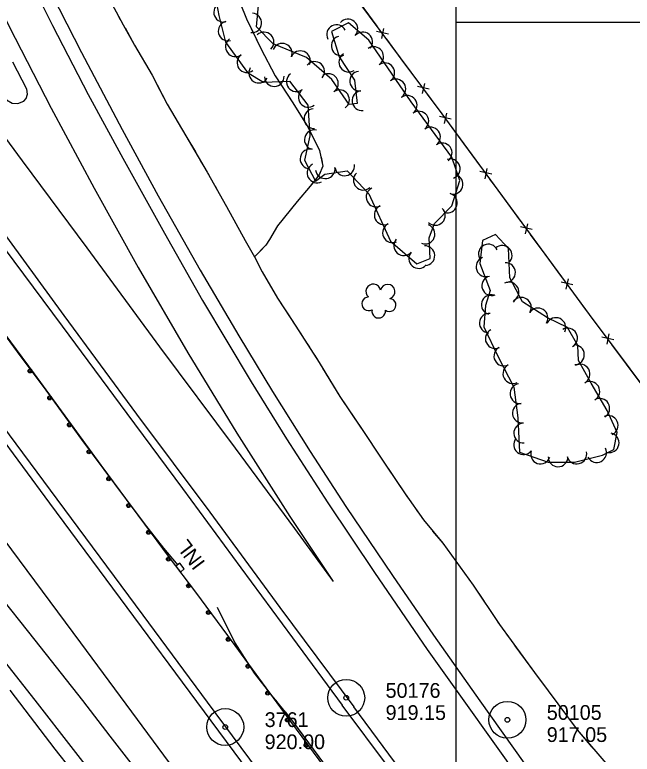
# Model space of a CAD drawing. Extents: x 353423 to 364002, y 127000 to 201942.
# Drawn here: x 359820.6 to 360071.5, y 131702.2 to 132002.9 of the extents above; entities that cross this region are included whole.
import ezdxf

# ---------------------------------------------------------------- set-up
doc = ezdxf.new("R2010")
doc.units = 0
for name, color, linetype in [('E_DTM_SlopeBottom', 7, 'Continuous'), ('E_DTM_SlopeTop', 7, 'Continuous'), ('E_FEN_Generic', 7, 'Continuous'), ('E_LAND_TreeLine', 7, 'Continuous'), ('E_MISCPROP', 7, 'Continuous'), ('E_RDWY_AsphConc', 7, 'Continuous'), ('E_STRUCT_WingWall', 7, 'Continuous')]:
    doc.layers.add(name, color=color, linetype=linetype)

msp = doc.modelspace()

# ---------------------------------------------------------------- linework, layer by layer
at = {"layer": 'E_DTM_SlopeBottom'}
for p, q in [((359972.44, 131995.06), (359967.62, 131996.12)), ((359969.73, 131993.27), (359970.62, 131997.4)), ((359986.31, 131970.87), (359987.2, 131975.01)), ((359989.01, 131972.66), (359984.2, 131973.72)), ((359995.24, 131958.78), (359996.15, 131962.91)), ((359997.95, 131960.55), (359993.14, 131961.64)), ((360014.4, 131938.07), (360009.59, 131939.15)), ((360011.68, 131936.29), (360012.59, 131940.42)), ((360028.18, 131913.83), (360029.08, 131917.96)), ((360030.89, 131915.61), (360026.08, 131916.69)), ((360047.39, 131893.16), (360042.57, 131894.24)), ((360044.67, 131891.38), (360045.57, 131895.51)), ((360061.27, 131868.99), (360062.14, 131873.13)), ((360063.97, 131870.79), (360059.15, 131871.83))]:
    msp.add_line(p, q, dxfattribs=at)
for points in [[(359994.23, 131962.69), (359952.2, 132019.47), (359914.96, 132070.63), (359879.25, 132119.71), (359869.92, 132132.28), (359846.86, 132192.53), (359828.18, 132241.38), (359813.12, 132280.33), (359807.45, 132296.37), (359796.4, 132325.26), (359763.05, 132412.67), (359729.64, 132499.02), (359699.93, 132578.43), (359671.73, 132653.26)], [(359967.82, 131998.38), (359961.08, 132007.48)], [(359977.66, 131985.09), (359971.73, 131993.09)], [(359984.39, 131975.99), (359977.66, 131985.09)], [(359994.23, 131962.69), (359988.31, 131970.7)], [(360168.57, 131726.41), (360146.27, 131756.69), (360118.24, 131794.76), (360087.55, 131836.32), (360054.15, 131881.02), (360015.47, 131933.65), (359994.23, 131962.69)], [(360003.11, 131950.55), (359997.23, 131958.59)], [(360009.79, 131941.42), (360003.11, 131950.55)], [(360019.57, 131928.08), (360015.47, 131933.65), (360013.68, 131936.1)], [(360026.27, 131918.95), (360019.57, 131928.08)], [(360036.07, 131905.62), (360030.17, 131913.65)], [(360042.77, 131896.5), (360036.07, 131905.62)], [(360052.57, 131883.18), (360046.67, 131891.2)], [(360059.33, 131874.09), (360054.15, 131881.02), (360052.57, 131883.18)], [(360069.23, 131860.85), (360063.27, 131868.82)], [(360076, 131851.78), (360069.23, 131860.85)], [(359887.91, 131776.33), (359889.48, 131777.56), (359887.63, 131779.92), (359886.06, 131778.68), (359887.91, 131776.33)]]:
    msp.add_lwpolyline(points, dxfattribs=at)
at = {"layer": 'E_DTM_SlopeTop'}
for points in [[(359296.04, 132656.2), (359327.36, 132613.62), (359357.21, 132573.34), (359387.83, 132532.04), (359420.96, 132487.16), (359453.44, 132443.29), (359480.05, 132407.27), (359517.09, 132357.33), (359543.42, 132321.88), (359571.35, 132284.17), (359599.99, 132245.46), (359627.75, 132207.82), (359655.85, 132169.95), (359684.1, 132131.8), (359713.89, 132091.57), (359740.72, 132055.1), (359769.42, 132016.5), (359798.55, 131977.39), (359823.57, 131943.56), (359849.91, 131908.1), (359879.42, 131867.94), (359910.1, 131826.75), (359934.24, 131793.99), (359949.98, 131772.5)], [(359894.52, 131723.73), (359866.32, 131761.93), (359834.77, 131804.35), (359801.8, 131849.06), (359771.18, 131890.36), (359741.61, 131930.36), (359706.83, 131977.37), (359677.25, 132017.15), (359645.21, 132060.41), (359616.57, 132099.29), (359584.47, 132142.49), (359551.44, 132186.98), (359516.16, 132234.78), (359477.26, 132287.18), (359438.91, 132339.08), (359394.26, 132399.62), (359356.73, 132450.28), (359318.1, 132502.23), (359283.37, 132549.19), (359243.7, 132602.83), (359207.65, 132651.41)], [(359449.12, 132409.2), (359470.8, 132379.85), (359494.5, 132347.87), (359517.49, 132316.9), (359547.17, 132276.9), (359572.24, 132242.9), (359598.91, 132206.77), (359623.16, 132174.01), (359647.03, 132141.86), (359674.62, 132104.55), (359700.41, 132069.65), (359726.69, 132034.19), (359755.34, 131995.76), (359785.73, 131954.75), (359813.39, 131917.61), (359840.54, 131880.58), (359870.11, 131840.52), (359899.85, 131800.63), (359928.33, 131761.92), (359958.37, 131721.52)], [(359458.15, 132391.51), (359482.94, 132357.62), (359509.06, 132322.72), (359533.32, 132290.35), (359554.33, 132261.68), (359577.87, 132229.81), (359599.59, 132200.53), (359624.12, 132167.31), (359650.84, 132131.46), (359672.46, 132102.12), (359694.57, 132072.22), (359715.85, 132043.32), (359739.28, 132011.9), (359764.96, 131977.01), (359794.26, 131937.73), (359816.26, 131908), (359839.86, 131876.35), (359866.08, 131840.78), (359888.69, 131810.32), (359912.39, 131778), (359933.4, 131749.61), (359953.69, 131722.15)], [(359898.92, 131723.42), (359872.8, 131758.76), (359846.3, 131794.45), (359818.43, 131832.09), (359795, 131863.74), (359772.17, 131894.54), (359743.48, 131933.36), (359717.7, 131968.37), (359690.1, 132005.9), (359664.2, 132040.3), (359638.9, 132074.46), (359610.49, 132113.12), (359579.6, 132154.64), (359555.84, 132186.89), (359530, 132221.9), (359503.11, 132258.09), (359475.08, 132296.24), (359444.41, 132337.76)], [(359868.2, 131719.43), (359847.41, 131747.54), (359825.57, 131776.88), (359796.6, 131815.87), (359765.6, 131857.67), (359742.12, 131889.93), (359715.95, 131925.49), (359687.37, 131963.93), (359656.97, 132005.11), (359627.89, 132044.33), (359595.85, 132087.53), (359565.18, 132128.99), (359537.2, 132166.91), (359505.6, 132209.55), (359474.16, 132252.13), (359447.44, 132288.27)], [(359700.05, 132273.28), (359712.8, 132237.69), (359725.4, 132203.32), (359735.76, 132177.49), (359746.99, 132150.6), (359759.54, 132121.8), (359773.57, 132090.93), (359785.92, 132064.69), (359801.61, 132032.3), (359818.33, 131998.22), (359835.34, 131964.98), (359852.8, 131932.45), (359870.66, 131900.2), (359890.88, 131865.53), (359910.85, 131832.76), (359932.41, 131798.96), (359949.98, 131772.5)], [(359592.85, 132271.02), (359618.41, 132235.79), (359644.81, 132200.77), (359666.15, 132171.99), (359690.78, 132138.33), (359713.66, 132107.36), (359735.88, 132077.57), (359760.85, 132044.13), (359785.15, 132010.81), (359805.83, 131982.59), (359812.81, 131973.72), (359817.2, 131968.39), (359819.47, 131967.02), (359821.81, 131966.89), (359824.21, 131967.81), (359825.22, 131968.91), (359825.69, 131970.63), (359825.49, 131972.75), (359823.63, 131976.39), (359819.82, 131983.66)], [(359723.98, 132253.55), (359734.47, 132224.72), (359743.46, 132201.25), (359753.66, 132175.87), (359763.64, 132152.33), (359774.89, 132126.88), (359785.49, 132103.17), (359796.86, 132078.56), (359809.93, 132051.09), (359823, 132024.51), (359835.91, 131998.55), (359850.36, 131970.51), (359864.45, 131944.59), (359881.37, 131914.12), (359896.89, 131886.8), (359916.63, 131853.64), (359931.02, 131830.55), (359947.83, 131804.43), (359966.72, 131776.07), (359988.15, 131744.83), (360003.08, 131723.98)], [(359730.51, 132251.03), (359743.22, 132216.83), (359756.28, 132183.41), (359769.95, 132150.92), (359783.7, 132119.94), (359798.77, 132086.94), (359816.13, 132050.52), (359832.64, 132017.17), (359847.63, 131987.57), (359864.22, 131956.33), (359878.9, 131929.35), (359895.89, 131899.11), (359911.69, 131872.44), (359925.25, 131849.7), (359940.63, 131825.32), (359955.08, 131803.02), (359974.09, 131774.93), (359990.7, 131750.65), (360009.57, 131723.99)], [(359848.21, 131724.01), (359828.93, 131748.59), (359812.62, 131768.97), (359793.78, 131792.21), (359774.6, 131815.52), (359754.43, 131839.17), (359744.04, 131851.3), (359727.16, 131870.29), (359705.92, 131893.68), (359681.76, 131919.04), (359656.38, 131945.02), (359634.73, 131966.57), (359610.44, 131989.93), (359588.34, 132010.76), (359565.03, 132032.22), (359539.45, 132055.04), (359511.05, 132079.94), (359486.28, 132100.8), (359462, 132120.43), (359439.65, 132138.15)], [(359829.79, 131722.95), (359815.52, 131741.24), (359796.41, 131765.22), (359779.05, 131786.77), (359761.9, 131807.33), (359743.27, 131829.13), (359722.54, 131852.67), (359704.55, 131872.62), (359689.86, 131888.7), (359672.14, 131907.09), (359654.35, 131925.48), (359637.61, 131942.19), (359622.74, 131956.82), (359604.84, 131974.1), (359580.59, 131997.01), (359560.31, 132015.88), (359542.62, 132031.93), (359524.86, 132047.65), (359508.32, 132062.07), (359490.01, 132077.74), (359471.36, 132093.36), (359448.96, 132111.3)], [(360013.42, 131478.34), (359990.18, 131508.19), (359960.04, 131546.84), (359929.84, 131585.6), (359902.65, 131620.65), (359863.57, 131670.72), (359837.05, 131704.29), (359818.68, 131728.32)], [(360010.51, 131490.72), (359990.1, 131516.98), (359965.39, 131548.72), (359947.29, 131571.89), (359918.85, 131608.2), (359891.94, 131643.25), (359866.78, 131675.39), (359843.48, 131705.36), (359829.79, 131722.95)], [(360010.09, 131515.87), (359987.25, 131545.27), (359962.48, 131577.01), (359939.3, 131606.81), (359913.57, 131639.74), (359884.96, 131676.62), (359859.4, 131709.56), (359848.21, 131724.01)], [(360002.77, 131577.44), (359979.31, 131608.89), (359955.06, 131642.05), (359915.55, 131695.36), (359894.52, 131723.73)], [(360004.85, 131580.55), (359984.1, 131608.63), (359955.73, 131646.88), (359916.04, 131700.24), (359898.92, 131723.42)], [(359999.42, 131660.51), (359972.51, 131696.92), (359953.69, 131722.15)], [(360003.08, 131723.98), (360026.59, 131690.8)], [(360009.57, 131723.99), (360027.6, 131698.56)], [(360002.79, 131537.75), (359978.38, 131570.74), (359948.81, 131610.58), (359916.65, 131653.79), (359881.09, 131701.79), (359868.2, 131719.43)], [(360000.03, 131665.19), (359982.22, 131689.22), (359958.37, 131721.52)]]:
    msp.add_lwpolyline(points, dxfattribs=at)
at = {"layer": 'E_FEN_Generic'}
msp.add_lwpolyline([(359902.34, 132009.29), (359903.55, 132002.68), (359906.26, 131991.78), (359915.21, 131979.52), (359921.59, 131975.6), (359932.21, 131975.92), (359939.64, 131966.16), (359940.54, 131953.73), (359938.29, 131943.82), (359942.82, 131935.21), (359946.62, 131938.17), (359955.71, 131939.53), (359964.43, 131930.19), (359973.3, 131910.91), (359983.99, 131901.63), (359989.41, 131903.8), (359988.99, 131912.28), (359991.19, 131918), (359998.2, 131925.2), (360001.4, 131935.61), (359998.16, 131945.07), (359981.61, 131967.51), (359964.41, 131992.61), (359956.18, 131999.72), (359949.29, 131996.2), (359952.35, 131985.89), (359958.59, 131976.32), (359959.68, 131966.89), (359956.43, 131966.41), (359949.43, 131976.67), (359939.16, 131985.52), (359925.61, 131991.06), (359918.83, 131998.07), (359920.1, 132012.69)], dxfattribs=at)
msp.add_lwpolyline([(360048.07, 131820.99), (360059.43, 131823.83), (360064.01, 131826.2), (360065.39, 131833.01), (360061.31, 131841.99), (360054.79, 131853.13), (360049.62, 131862.31), (360049.39, 131868.5), (360045.18, 131875.81), (360037.02, 131879.73), (360026.85, 131886.22), (360021.71, 131895.98), (360021.23, 131907.86), (360015.97, 131913.62), (360010.63, 131911.1), (360009.6, 131901.86), (360013.7, 131890.79), (360011.93, 131884.66), (360011.17, 131875.99), (360017.08, 131863.86), (360023.4, 131851.56), (360024.95, 131839.06), (360025.7, 131825), (360037.29, 131821.06)], close=True, dxfattribs=at)
for centre, radius, start, end in [((359905.45, 132003.97), 4, 100.4176, 280.4023), ((359916.87, 131999.67), 4, 265.0467, 85.0314), ((359907.29, 131996.32), 4, 103.9599, 283.9446), ((359951.34, 131994.89), 4, 27.0936, 207.0783), ((359955.94, 131997.16), 4, 319.1843, 139.1689), ((359921.89, 131991.89), 4, 314.0383, 134.0229), ((359962, 131991.93), 4, 319.1843, 139.1689), ((359910.22, 131989.91), 4, 126.1347, 306.1194), ((359953.23, 131990.3), 4, 106.5304, 286.5151), ((359929.28, 131987.29), 4, 337.7794, 157.764), ((359966.43, 131985.97), 4, 304.4258, 124.4105), ((359914.93, 131983.45), 4, 126.1347, 306.1194), ((359936.68, 131984.27), 4, 337.7794, 157.764), ((359956.3, 131983.67), 4, 123.0842, 303.0689), ((359942.47, 131979.9), 4, 319.2641, 139.2488), ((359970.95, 131979.37), 4, 304.4258, 124.4105), ((359919.71, 131979.21), 4, 148.4304, 328.4151), ((359926.03, 131977.83), 4, 181.7032, 1.6879), ((359935.02, 131975.69), 4, 127.3042, 307.2889), ((359948.05, 131974.98), 4, 304.2891, 124.2738), ((359960.74, 131975.97), 4, 96.6473, 276.632), ((359975.47, 131972.77), 4, 304.4258, 124.4105), ((359939.86, 131969.32), 4, 127.3042, 307.2889), ((359952.56, 131968.37), 4, 304.2891, 124.2738), ((359961.66, 131968.03), 4, 96.6473, 276.632), ((359980.04, 131966.12), 4, 306.4048, 126.3895), ((359942.13, 131960.71), 4, 94.1251, 274.1098), ((359984.78, 131959.68), 4, 306.4048, 126.3895), ((359989.53, 131953.24), 4, 306.4048, 126.3895), ((359942.32, 131952.14), 4, 77.2319, 257.2166), ((359994.28, 131946.8), 4, 306.4048, 126.3895), ((359940.55, 131944.34), 4, 77.2319, 257.2166), ((359997.57, 131940.32), 4, 288.9159, 108.9005), ((359943.4, 131938.61), 4, 117.7632, 297.7479), ((359954.66, 131941.49), 4, 188.5055, 8.4902), ((359946.75, 131940.31), 4, 188.5055, 8.4902), ((359962.19, 131935.65), 4, 133.0367, 313.0213), ((359998.72, 131934.02), 4, 252.9538, 72.9384), ((359967.37, 131928.81), 4, 114.7183, 294.703), ((359996.37, 131926.38), 4, 252.9538, 72.9384), ((359970.71, 131921.55), 4, 114.7183, 294.703), ((359991.53, 131921.35), 4, 225.7745, 45.7592), ((359974.05, 131914.28), 4, 114.7183, 294.703), ((359987.31, 131913.75), 4, 248.9319, 68.9165), ((359978.64, 131909.05), 4, 139.056, 319.0407), ((359987.25, 131904.96), 4, 272.8624, 92.847), ((360013.02, 131905.65), 4, 25.2355, 205.2202), ((360018.68, 131905.09), 4, 312.4398, 132.4244), ((359984.68, 131903.81), 4, 139.056, 319.0407), ((360012.04, 131900.45), 4, 110.3351, 290.3198), ((360020, 131898.11), 4, 272.3361, 92.3208), ((360014.4, 131892.76), 4, 110.3351, 290.3198), ((359966.25, 131890.45), 2.97, 8.541, 229.7749), ((359972.1, 131890.35), 2.97, 286.1918, 169.1651), ((360021.43, 131890.22), 4, 297.7837, 117.7684), ((359964.4, 131885.4), 2.78, 91.5119, 299.2849), ((359972.88, 131884.88), 2.61, 230.8971, 88.8297), ((360014.22, 131885.04), 4, 73.9078, 253.8925), ((360026.47, 131883.98), 4, 327.4802, 147.4648), ((359968.48, 131882.41), 2.78, 168.1889, 9.2), ((360013.41, 131877.51), 4, 85.006, 264.9906), ((360033.22, 131879.68), 4, 327.4802, 147.4648), ((360040.46, 131875.76), 4, 334.3453, 154.33), ((360045.25, 131871.5), 4, 299.9525, 119.9372), ((360015.81, 131871.25), 4, 115.9837, 295.9684), ((360019.31, 131864.11), 4, 117.1944, 297.1791), ((360048.02, 131864.67), 4, 272.1733, 92.158), ((360022.96, 131856.99), 4, 117.1944, 297.1791), ((360050.32, 131856.81), 4, 299.3495, 119.3342), ((360025.84, 131848.87), 4, 97.0829, 277.0676), ((360054.29, 131849.83), 4, 300.3525, 120.3372), ((360058.33, 131842.93), 4, 300.3525, 120.3372), ((360026.83, 131840.93), 4, 97.0829, 277.0676), ((360061.75, 131835.94), 4, 294.4388, 114.4235), ((360027.38, 131832.81), 4, 93.0715, 273.0561), ((360027.31, 131828.1), 4, 141.3106, 321.2952), ((360062.14, 131828.87), 4, 258.619, 78.6037), ((360034.22, 131824.31), 4, 161.2339, 341.2185), ((360049, 131824.28), 4, 194.0287, 14.0134), ((360057.05, 131824.86), 4, 207.3624, 27.3471), ((360041.35, 131823.13), 4, 179.64, 359.6247)]:
    msp.add_arc(centre, radius, start, end, dxfattribs=at)
at = {"layer": 'E_LAND_TreeLine'}
for p, q in [((360000, 131000), (360000, 133500)), ((360000, 132000), (364000, 132000))]:
    msp.add_line(p, q, dxfattribs=at)
at = {"layer": 'E_MISCPROP'}
for points in [[(359932.77, 131715.59), (359907.15, 131750.48), (359894.1, 131768.15), (359883.51, 131782.24), (359855.63, 131819.77), (359828.65, 131856.91), (359794.13, 131903.25), (359773.45, 131931.92), (359764.25, 131945.43), (359758.23, 131955.29), (359751.74, 131967.49)], [(359932.77, 131715.59), (359907.15, 131750.48), (359894.1, 131768.15), (359883.51, 131782.24), (359855.63, 131819.77), (359828.65, 131856.91), (359794.13, 131903.25), (359773.45, 131931.92), (359764.25, 131945.43), (359758.23, 131955.29), (359751.74, 131967.49)], [(359996.88, 131629.11), (359965.39, 131671.35), (359932.77, 131715.59)], [(359996.88, 131629.11), (359965.39, 131671.35), (359932.77, 131715.59)]]:
    msp.add_lwpolyline(points, dxfattribs=at)
for centre, radius in [((359826.79, 131858.08), 0.79), ((359826.76, 131858.11), 0.398), ((359834.77, 131847.13), 0.79), ((359834.75, 131847.17), 0.398), ((359842.75, 131836.16), 0.79), ((359842.72, 131836.19), 0.398), ((359850.72, 131825.19), 0.79), ((359850.7, 131825.22), 0.398), ((359858.75, 131814.25), 0.79), ((359858.73, 131814.28), 0.398), ((359866.84, 131803.36), 0.79), ((359866.81, 131803.39), 0.398), ((359874.92, 131792.47), 0.79), ((359874.9, 131792.5), 0.398), ((359883.01, 131781.58), 0.79), ((359882.99, 131781.61), 0.398), ((359891.17, 131770.74), 0.79), ((359891.14, 131770.77), 0.398), ((359899.25, 131759.85), 0.79), ((359899.22, 131759.89), 0.398), ((359907.3, 131748.94), 0.79), ((359907.28, 131748.98), 0.398), ((359915.33, 131738.01), 0.79), ((359915.3, 131738.05), 0.398), ((359923.36, 131727.08), 0.79), ((359923.33, 131727.11), 0.398), ((359931.38, 131716.14), 0.79), ((359931.36, 131716.18), 0.398), ((359938.92, 131705.92), 0.79), ((359938.89, 131705.96), 0.398)]:
    msp.add_circle(centre, radius, dxfattribs=at)
at = {"layer": 'E_RDWY_AsphConc'}
for centre, radius in [((359955.27, 131725.17), 7.5), ((359955.27, 131725.17), 7.5), ((359955.27, 131725.17), 7.5), ((359955.27, 131725.17), 7.5), ((359955.27, 131725.17), 0.96), ((359955.27, 131725.17), 0.96), ((359955.27, 131725.17), 0.96), ((359955.27, 131725.17), 0.96), ((360020.76, 131716.21), 7.5), ((360020.76, 131716.21), 7.5), ((360020.76, 131716.21), 7.5), ((360020.76, 131716.21), 7.5), ((359906.12, 131713.29), 7.5), ((359906.12, 131713.29), 7.5), ((359906.12, 131713.29), 7.5), ((359906.12, 131713.29), 7.5), ((360020.76, 131716.21), 0.96), ((360020.76, 131716.21), 0.96), ((360020.76, 131716.21), 0.96), ((360020.76, 131716.21), 0.96), ((359906.12, 131713.29), 0.96), ((359906.12, 131713.29), 0.96), ((359906.12, 131713.29), 0.96), ((359906.12, 131713.29), 0.96)]:
    msp.add_circle(centre, radius, dxfattribs=at)
at = {"layer": 'E_STRUCT_WingWall'}
for points in [[(359860.28, 132118.03), (359866.37, 132104.22), (359874.15, 132087.44), (359880.34, 132073.07), (359886.49, 132060.25), (359894.39, 132044.03), (359901.74, 132028.98), (359909.81, 132013.53), (359914.75, 132001.29), (359920.58, 131989.26), (359926.35, 131978.12), (359933.58, 131967.08), (359939.77, 131957.05), (359944.45, 131947.76), (359945.78, 131941.4), (359944.29, 131937.85), (359940.57, 131933.27), (359935.38, 131927.04), (359927.32, 131917.1), (359924.03, 131911.52), (359922.67, 131909.2), (359917.96, 131904.48)], [(359858.1, 132010.99), (359864.65, 131998.89), (359869.29, 131990.61), (359876.4, 131978.4), (359882.5, 131966.53), (359890.1, 131953.76), (359898.74, 131938.97), (359906.6, 131925.03), (359914.14, 131911.14), (359917.96, 131904.48), (359921.18, 131898.43), (359927.3, 131887.63), (359934.8, 131876.3), (359944.27, 131861.51), (359952.7, 131847.67), (359961.74, 131834.27), (359969.73, 131822.16), (359979.21, 131808.09), (359986.72, 131797.49), (359994.47, 131788.01)], [(359862.5, 132002.85), (359863.46, 132001.09)], [(359915.67, 131999.38), (359920.58, 131989.26), (359926.35, 131978.12), (359929.21, 131973.76)], [(359865.38, 131997.59), (359869.29, 131990.61), (359876.4, 131978.4), (359879.54, 131972.29)], [(359879.54, 131972.29), (359882.5, 131966.53), (359890.1, 131953.76), (359893.97, 131947.14)], [(359929.21, 131973.76), (359933.58, 131967.08), (359939.77, 131957.05), (359943.92, 131948.81)], [(359945.03, 131944.99), (359945.44, 131943.04)], [(359895.98, 131943.69), (359896.99, 131941.96)], [(359899, 131938.5), (359899.99, 131936.76)], [(359944.88, 131939.25), (359944.29, 131937.85), (359943.99, 131937.48)], [(359901.95, 131933.27), (359902.93, 131931.53)], [(359941.47, 131934.37), (359940.57, 131933.27), (359940.2, 131932.83)], [(359937.64, 131929.75), (359935.38, 131927.04), (359927.32, 131917.1), (359924.03, 131911.52), (359922.67, 131909.2), (359920.19, 131906.72)], [(359904.9, 131928.05), (359906.6, 131925.03), (359914.14, 131911.14), (359917.96, 131904.48), (359918.92, 131902.67)], [(359920.19, 131906.72), (359917.96, 131904.48)], [(359918.92, 131902.67), (359921.18, 131898.43), (359927.3, 131887.63), (359933.81, 131877.8)], [(359805.88, 131887.17), (359806.07, 131886.94), (359818.57, 131869.88), (359823.09, 131863.83)], [(359935.99, 131874.45), (359937.07, 131872.77)], [(359818.57, 131869.88), (359833.17, 131850.3), (359847.7, 131830.27), (359861.04, 131812.15), (359873.22, 131796.05), (359881.07, 131786), (359886.18, 131779.94), (359886.73, 131779.26)], [(359939.22, 131869.4), (359940.3, 131867.71)], [(359823.09, 131863.83), (359833.17, 131850.3), (359840.29, 131840.49)], [(359942.46, 131864.34), (359943.54, 131862.66)], [(359945.64, 131859.26), (359952.7, 131847.67), (359961.33, 131834.88)], [(359842.64, 131837.25), (359843.82, 131835.63)], [(359961.33, 131834.88), (359961.74, 131834.27), (359969.73, 131822.16), (359977.42, 131810.75)], [(359846.17, 131832.39), (359847.34, 131830.77)], [(359849.71, 131827.55), (359850.9, 131825.94)], [(359853.27, 131822.72), (359861.04, 131812.15), (359870.62, 131799.48)], [(359979.67, 131807.44), (359980.83, 131805.81)], [(359983.14, 131802.55), (359984.29, 131800.92)], [(359870.62, 131799.48), (359873.22, 131796.05), (359881.07, 131786), (359886.18, 131779.94), (359886.73, 131779.26)], [(359986.61, 131797.65), (359986.72, 131797.49), (359987.86, 131796.1)], [(359990.39, 131793), (359994.47, 131788.01)], [(359994.47, 131788.01), (360006.91, 131770.93), (360017.55, 131754.94), (360031.76, 131735.42), (360037.33, 131728.03)], [(359994.47, 131788.01), (360006.91, 131770.93), (360011.27, 131764.38)], [(359902.84, 131762.06), (359910.03, 131747.51), (359917.86, 131735.24), (359925.05, 131726.03), (359933.47, 131715.64)], [(359902.84, 131762.06), (359910.03, 131747.51), (359916.9, 131736.74)], [(360013.48, 131761.05), (360014.59, 131759.39)], [(360016.81, 131756.06), (360017.55, 131754.94), (360017.94, 131754.41)], [(360020.29, 131751.17), (360021.47, 131749.56)], [(360023.83, 131746.33), (360031.76, 131735.42), (360037.33, 131728.03)], [(359919.22, 131733.49), (359920.45, 131731.92)], [(359922.91, 131728.76), (359924.15, 131727.19)], [(360037.33, 131728.03), (360049.06, 131712.08), (360067.49, 131690.73)], [(360037.33, 131728.03), (360049.06, 131712.08), (360055.07, 131705.12)], [(359926.64, 131724.06), (359927.9, 131722.51)], [(359930.42, 131719.4), (359933.47, 131715.64)], [(359933.47, 131715.64), (359956.37, 131684.65), (359982.3, 131648.13), (359998.89, 131625.43)], [(359933.47, 131715.64), (359950.7, 131692.32)]]:
    msp.add_lwpolyline(points, dxfattribs=at)

# ---------------------------------------------------------------- texts
at = {"layer": 'E_DTM_SlopeBottom'}
msp.add_text('INL', height=6, rotation=127.1174, dxfattribs=at).set_placement((359898.26, 131780.15))
at = {"layer": 'E_RDWY_AsphConc'}
for s, p in [('50176', (359971.27, 131725.17)), ('50176', (359971.27, 131725.17)), ('50176', (359971.27, 131725.17)), ('50176', (359971.27, 131725.17)), ('919.15', (359971.27, 131716.17)), ('919.15', (359971.27, 131716.17)), ('919.15', (359971.27, 131716.17)), ('919.15', (359971.27, 131716.17)), ('50105', (360036.76, 131716.21)), ('50105', (360036.76, 131716.21)), ('50105', (360036.76, 131716.21)), ('50105', (360036.76, 131716.21)), ('3761', (359922.12, 131713.29)), ('3761', (359922.12, 131713.29)), ('3761', (359922.12, 131713.29)), ('3761', (359922.12, 131713.29)), ('917.05', (360036.76, 131707.21)), ('917.05', (360036.76, 131707.21)), ('917.05', (360036.76, 131707.21)), ('917.05', (360036.76, 131707.21)), ('920.00', (359922.12, 131704.29)), ('920.00', (359922.12, 131704.29)), ('920.00', (359922.12, 131704.29)), ('920.00', (359922.12, 131704.29))]:
    msp.add_text(s, height=6, dxfattribs=at).set_placement(p)

doc.saveas('drawing.dxf')
